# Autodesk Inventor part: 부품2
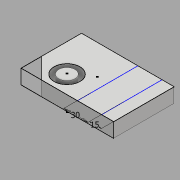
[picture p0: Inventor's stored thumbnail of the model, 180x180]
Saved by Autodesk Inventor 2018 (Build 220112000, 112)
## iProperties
Created: 2019-06
Part Number: 부품2
Material: 일반
Document SubType Name: Modeling
Designer: 6507_14
Density: 1 g/cm^3
Appearance: 기본값
Author: 6507_14
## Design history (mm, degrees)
sketch "스케치1"
  geometry: L1 (-57.5, 37.5)-(57.5, 37.5); L2 (57.5, 37.5)-(57.5, -37.5); L3 (57.5, -37.5)-(-57.5, -37.5); L4 (-57.5, -37.5)-(-57.5, 37.5); L5 (-57.5, 37.5)-(57.5, -37.5); L6 (57.5, 37.5)-(-57.5, -37.5); C1 r 10 at (-130.855, -42.371); C2 r 16 at (-130.855, -42.371); 1 further point
  constraints: 12 end point, 2 centre point, 2 midpoint, 2 parallel, 1 coincident, 1 horizontal, 1 perpendicular
  dimensions: "d0" = 115 distance of L2.end L3.end; "d1" = 75 distance of L1.end L2.end; "d11" = 20 diameter of C1; "d12" = 32 diameter of C2
extrude "돌출1" new body sketch "스케치1" distance "d13" = 18; taper "d14" = 0 deg
sketch "스케치2"
  geometry: L1 (57.5, 37.5)-(-57.5, 37.5) reference; L2 (-57.5, 37.5)-(-57.5, -37.5) reference; C1 r 10 at (-22.5, -15.5); C2 r 16 at (-22.5, -15.5); 1 further point
  constraints: 2 centre point, 1 coincident
  dimensions: "d19" = 20 diameter of C1; "d20" = 32 diameter of C2; "d21" = 53 distance from line of L1 C1.centre; "d22" = 35 distance from line of L2 C1.centre
sketch "스케치3"
  geometry: L1 (115, 0)-(0, 0) reference; L2 (115, 0)-(115, 18) reference; L3 (0, 18)-(115, 18) reference; L4 (0, 0)-(0, 18) reference; 1 further point
sketch "스케치4"
  geometry: L1 (57.5, 37.5)-(-57.5, 37.5) reference; L2 (-57.5, 37.5)-(-57.5, -37.5) reference; L3 (-57.5, -37.5)-(57.5, -37.5) reference; L4 (57.5, -37.5)-(57.5, 37.5) reference; 1 further point
sketch "스케치5"
  geometry: L1 (57.5, 37.5)-(-57.5, 37.5) reference; L2 (-57.5, 37.5)-(-57.5, -37.5) reference; L3 (-57.5, -37.5)-(57.5, -37.5) reference; L4 (57.5, -37.5)-(57.5, 37.5) reference; 1 further point
sketch "스케치6"
  geometry: L1 (-57.5, 37.5)-(-57.5, -37.5) reference; L2 (-57.5, -37.5)-(57.5, -37.5) reference; L3 (-32.5, -30.839)-(-32.5, -47.331); L4 (-32.5, -37.5)-(-57.5, -12.5); 1 further point
  constraints: 4 end point, 3 point on line, 1 perpendicular
  dimensions: "d24" = 25 distance between parallel lines of L1 L3; "d25" = 45 deg angle of L2 L4
extrude "돌출2" cut sketch "스케치6" extent not by distance; stored distance "d26" = 25; taper "d27" = 0 deg
sketch "스케치7"
  geometry: L1 (-57.5, -12.5)-(-32.5, -37.5) reference; L2 (-32.5, -37.5)-(57.5, -37.5) reference; L3 (57.5, -37.5)-(57.5, 37.5) reference; L4 (57.5, 37.5)-(-57.5, 37.5) reference; L5 (-57.5, 37.5)-(-57.5, -12.5) reference; 1 further point
sketch "스케치8"
  geometry: L1 (-57.5, -12.5)-(-32.5, -37.5) reference; L2 (-32.5, -37.5)-(57.5, -37.5) reference; L3 (57.5, -37.5)-(57.5, 37.5) reference; L4 (57.5, 37.5)-(-57.5, 37.5) reference; L5 (-57.5, 37.5)-(-57.5, -12.5) reference; L6 (42.5, 37.5)-(42.5, -37.5); L7 (12.5, 37.5)-(12.5, -37.5); 1 further point
  constraints: 4 end point, 3 point on line, 2 vertical, 1 midpoint
  dimensions: "d29" = 15 distance between parallel lines of L3 L6; "d30" = 30 distance between parallel lines of L6 L7
sketch "스케치9"
  geometry: L1 (-57.5, -12.5)-(-32.5, -37.5) reference; L2 (-32.5, -37.5)-(57.5, -37.5) reference; L3 (57.5, -37.5)-(57.5, 37.5) reference; L4 (57.5, 37.5)-(-57.5, 37.5) reference; L5 (-57.5, 37.5)-(-57.5, -12.5) reference; 1 further point
extrude "돌출3" cut sketch "스케치2" extent not by distance; stored distance "d31" = 25; taper "d32" = 0 deg
sketch "스케치10"
  geometry: L1 (-57.5, -12.5)-(-32.5, -37.5) reference; L2 (-32.5, -37.5)-(57.5, -37.5) reference; L3 (57.5, -37.5)-(57.5, 37.5) reference; L4 (57.5, 37.5)-(-57.5, 37.5) reference; L5 (-57.5, 37.5)-(-57.5, -12.5) reference; C1 r 16 at (-22.5, -15.5) reference; 1 further point
sketch "스케치11"
  geometry: L1 (-57.5, -12.5)-(-32.5, -37.5) reference; L2 (-32.5, -37.5)-(57.5, -37.5) reference; L3 (57.5, -37.5)-(57.5, 37.5) reference; L4 (57.5, 37.5)-(-57.5, 37.5) reference; L5 (-57.5, 37.5)-(-57.5, -12.5) reference; C1 r 16 at (-22.5, -15.5) reference; 1 further point
node "솔리드1"
